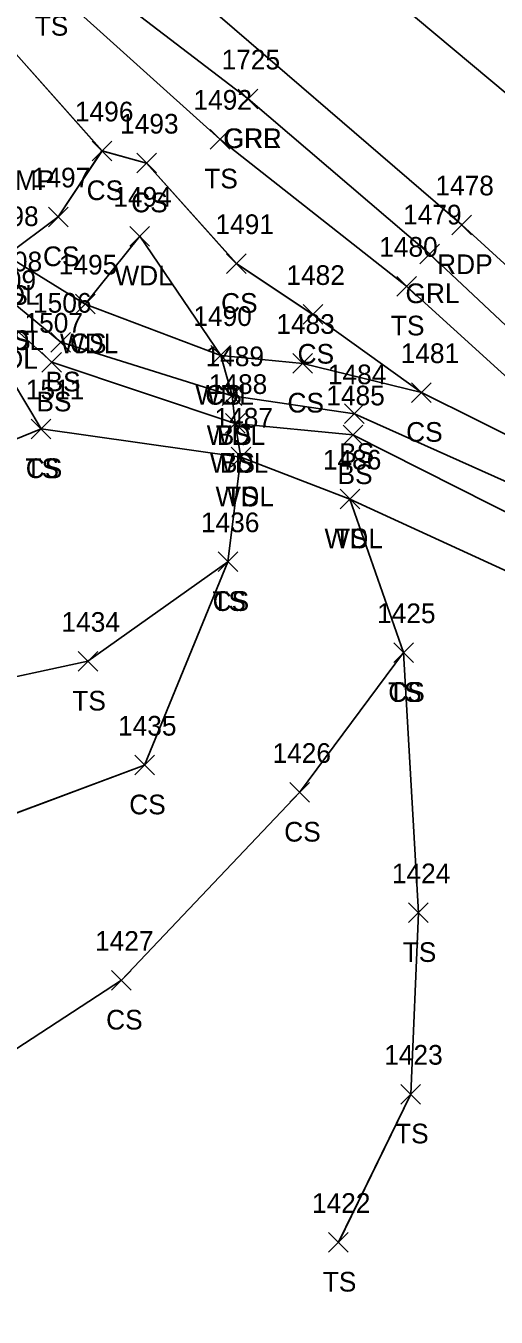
# Model space of a CAD drawing. Extents: x 1415642 to 1422021, y 544543 to 547232.
# Drawn here: x 1416137.5 to 1416185.4, y 546673.7 to 546804.9 of the extents above; entities that cross this region are included whole.
import ezdxf

# ---------------------------------------------------------------- set-up
doc = ezdxf.new("R2010")
doc.units = 0
for name, color, linetype in [('D_C', 7, 'Continuous'), ('L_A', 7, 'Continuous'), ('L_I', 7, 'Continuous'), ('L_TIC', 7, 'Continuous'), ('LAWA', 7, 'Continuous'), ('LELB', 7, 'Continuous'), ('P_A', 7, 'Continuous'), ('P_I', 7, 'Continuous'), ('P_TIC', 7, 'Continuous'), ('PET', 7, 'Continuous'), ('PRC', 7, 'Continuous'), ('R_A', 7, 'Continuous'), ('R_I', 7, 'Continuous'), ('R_TIC', 7, 'Continuous'), ('RGR', 7, 'Continuous')]:
    doc.layers.add(name, color=color, linetype=linetype)

msp = doc.modelspace()

# ---------------------------------------------------------------- linework, layer by layer
at = {"layer": 'L_TIC'}
for points in [[(1416156.26, 546792.38), (1416158.26, 546794.38)], [(1416158.26, 546792.38), (1416156.26, 546794.38)], [(1416144.27, 546791.19), (1416146.27, 546793.19)], [(1416146.27, 546791.19), (1416144.27, 546793.19)], [(1416144.27, 546791.19), (1416146.27, 546793.19)], [(1416146.27, 546791.19), (1416144.27, 546793.19)], [(1416148.8, 546789.95), (1416150.8, 546791.95)], [(1416150.8, 546789.95), (1416148.8, 546791.95)], [(1416139.83, 546784.48), (1416141.83, 546786.48)], [(1416141.83, 546784.48), (1416139.83, 546786.48)], [(1416148.11, 546782.52), (1416150.11, 546784.52)], [(1416150.11, 546782.52), (1416148.11, 546784.52)], [(1416157.94, 546779.74), (1416159.94, 546781.74)], [(1416159.94, 546779.74), (1416157.94, 546781.74)], [(1416175.24, 546777.44), (1416177.24, 546779.44)], [(1416177.24, 546777.44), (1416175.24, 546779.44)], [(1416142.57, 546775.63), (1416144.57, 546777.63)], [(1416144.57, 546775.63), (1416142.57, 546777.63)], [(1416142.57, 546775.63), (1416144.57, 546777.63)], [(1416144.57, 546775.63), (1416142.57, 546777.63)], [(1416165.72, 546774.57), (1416167.72, 546776.57)], [(1416167.72, 546774.57), (1416165.72, 546776.57)], [(1416140.08, 546771.75), (1416142.08, 546773.75)], [(1416142.08, 546771.75), (1416140.08, 546773.75)], [(1416156.34, 546770.4), (1416158.34, 546772.4)], [(1416158.34, 546770.4), (1416156.34, 546772.4)], [(1416156.34, 546770.4), (1416158.34, 546772.4)], [(1416158.34, 546770.4), (1416156.34, 546772.4)], [(1416139.16, 546769.72), (1416141.16, 546771.72)], [(1416141.16, 546769.72), (1416139.16, 546771.72)], [(1416164.69, 546769.6), (1416166.69, 546771.6)], [(1416166.69, 546769.6), (1416164.69, 546771.6)], [(1416176.76, 546766.63), (1416178.76, 546768.63)], [(1416178.76, 546766.63), (1416176.76, 546768.63)], [(1416176.76, 546766.63), (1416178.76, 546768.63)], [(1416178.76, 546766.63), (1416176.76, 546768.63)], [(1416157.5, 546766.31), (1416159.5, 546768.31)], [(1416159.5, 546766.31), (1416157.5, 546768.31)], [(1416157.5, 546766.31), (1416159.5, 546768.31)], [(1416159.5, 546766.31), (1416157.5, 546768.31)], [(1416169.94, 546764.48), (1416171.94, 546766.48)], [(1416171.94, 546764.48), (1416169.94, 546766.48)], [(1416138.08, 546762.94), (1416140.08, 546764.94)], [(1416140.08, 546762.94), (1416138.08, 546764.94)], [(1416138.08, 546762.94), (1416140.08, 546764.94)], [(1416140.08, 546762.94), (1416138.08, 546764.94)], [(1416157.82, 546763.49), (1416159.82, 546765.49)], [(1416159.82, 546763.49), (1416157.82, 546765.49)], [(1416157.82, 546763.49), (1416159.82, 546765.49)], [(1416159.82, 546763.49), (1416157.82, 546765.49)], [(1416169.78, 546762.33), (1416171.78, 546764.33)], [(1416171.78, 546762.33), (1416169.78, 546764.33)], [(1416158.4, 546760.07), (1416160.4, 546762.07)], [(1416160.4, 546760.07), (1416158.4, 546762.07)], [(1416158.4, 546760.07), (1416160.4, 546762.07)], [(1416160.4, 546760.07), (1416158.4, 546762.07)], [(1416169.48, 546755.81), (1416171.48, 546757.81)], [(1416171.48, 546755.81), (1416169.48, 546757.81)], [(1416169.48, 546755.81), (1416171.48, 546757.81)], [(1416171.48, 546755.81), (1416169.48, 546757.81)], [(1416157.08, 546749.44), (1416159.08, 546751.44)], [(1416159.08, 546749.44), (1416157.08, 546751.44)], [(1416157.08, 546749.44), (1416159.08, 546751.44)], [(1416159.08, 546749.44), (1416157.08, 546751.44)], [(1416174.94, 546740.2), (1416176.94, 546742.2)], [(1416176.94, 546740.2), (1416174.94, 546742.2)], [(1416174.94, 546740.2), (1416176.94, 546742.2)], [(1416176.94, 546740.2), (1416174.94, 546742.2)], [(1416142.84, 546739.32), (1416144.84, 546741.32)], [(1416144.84, 546739.32), (1416142.84, 546741.32)], [(1416148.6, 546728.77), (1416150.6, 546730.77)], [(1416150.6, 546728.77), (1416148.6, 546730.77)], [(1416164.36, 546726), (1416166.36, 546728)], [(1416166.36, 546726), (1416164.36, 546728)], [(1416176.44, 546713.77), (1416178.44, 546715.77)], [(1416178.44, 546713.77), (1416176.44, 546715.77)], [(1416146.25, 546706.9), (1416148.25, 546708.9)], [(1416148.25, 546706.9), (1416146.25, 546708.9)], [(1416175.66, 546695.33), (1416177.66, 546697.33)], [(1416177.66, 546695.33), (1416175.66, 546697.33)], [(1416168.31, 546680.27), (1416170.31, 546682.27)], [(1416170.31, 546680.27), (1416168.31, 546682.27)]]:
    msp.add_lwpolyline(points, dxfattribs=at)
at = {"layer": 'LAWA'}
for points in [[(1416189.47, 546748.09), (1416170.48, 546756.81), (1416159.4, 546761.07), (1416158.82, 546764.49), (1416158.5, 546767.31), (1416157.34, 546771.4), (1416149.11, 546783.52), (1416143.57, 546776.63), (1416135.57, 546781.55), (1416136.01, 546776.95), (1416135.4, 546775.05), (1416133.21, 546773.7), (1416124.82, 546771.25), (1416110.47, 546763.9), (1416099.19, 546751.92), (1416087.77, 546744.35), (1416077.13, 546736.35), (1416057.11, 546720.87), (1416047.17, 546704.92)], [(1416189.46, 546748.09), (1416170.49, 546756.81), (1416159.39, 546761.07), (1416158.81, 546764.5), (1416158.51, 546767.31), (1416157.34, 546771.4), (1416149.11, 546783.52), (1416143.57, 546776.63), (1416135.57, 546781.55), (1416136.01, 546776.96), (1416135.4, 546775.05), (1416133.22, 546773.7), (1416124.83, 546771.26), (1416110.48, 546763.9), (1416099.2, 546751.92), (1416087.78, 546744.35), (1416077.14, 546736.35), (1416057.11, 546720.87), (1416047.18, 546704.93)]]:
    msp.add_lwpolyline(points, dxfattribs=at)
at = {"layer": 'LELB'}
for points in [[(1416200.69, 546756.25), (1416177.76, 546767.63), (1416166.72, 546775.57), (1416158.94, 546780.74), (1416149.8, 546790.95), (1416145.27, 546792.19), (1416135.47, 546803.24), (1416119.09, 546819.38), (1416087.86, 546845.73), (1416058.66, 546867.92), (1416017.63, 546898.15), (1415975.94, 546926.54), (1415961.59, 546937.35), (1415930.25, 546967.22), (1415904.85, 546987.6), (1415883.27, 547005.7), (1415850.56, 547030.99), (1415821.69, 547055.02)], [(1416200.69, 546756.25), (1416177.77, 546767.63), (1416166.72, 546775.57), (1416158.93, 546780.74), (1416149.8, 546790.95), (1416145.28, 546792.19), (1416135.47, 546803.24), (1416119.09, 546819.38), (1416087.87, 546845.73), (1416058.67, 546867.92), (1416017.63, 546898.16), (1415975.95, 546926.55), (1415961.6, 546937.34), (1415930.25, 546967.22), (1415904.86, 546987.6), (1415883.28, 547005.7), (1415850.57, 547030.99), (1415821.7, 547055.02)], [(1416413.88, 546519.84), (1416385.73, 546558.12), (1416356.85, 546595.36), (1416336.82, 546621.39), (1416300.66, 546661.66), (1416278.22, 546684.25), (1416249.88, 546714.04), (1416230.93, 546728.9), (1416221.86, 546737.5), (1416200.69, 546756.25), (1416176.24, 546778.44), (1416157.26, 546793.38), (1416140.02, 546808.9), (1416121.84, 546825.58), (1416090.2, 546848.7), (1416061.67, 546872.28), (1416021.03, 546902.96), (1415979.27, 546932.57), (1415964.6, 546940.59)], [(1416413.88, 546519.84), (1416385.73, 546558.12), (1416356.85, 546595.36), (1416336.82, 546621.39), (1416300.66, 546661.66), (1416278.22, 546684.25), (1416249.88, 546714.04), (1416230.93, 546728.9), (1416221.87, 546737.51), (1416200.69, 546756.25), (1416176.24, 546778.44), (1416157.26, 546793.38), (1416140.03, 546808.9), (1416121.84, 546825.58), (1416090.21, 546848.7), (1416061.68, 546872.28), (1416021.04, 546902.96), (1415979.28, 546932.57), (1415964.61, 546940.59)], [(1416145.27, 546792.19), (1416140.83, 546785.48), (1416135.57, 546781.55), (1416134.13, 546786.33), (1416133.18, 546791.55), (1416133.27, 546797.31), (1416128.67, 546801.95), (1416121.92, 546800.59), (1416115.75, 546796.75), (1416101.26, 546800.37), (1416080.07, 546796.23), (1416060.24, 546785.43), (1416047.26, 546780.09), (1416047.59, 546762.69), (1416049.58, 546754.22), (1416036.94, 546750.51), (1416008.63, 546746.22)], [(1416145.28, 546792.19), (1416140.83, 546785.48), (1416135.57, 546781.55), (1416134.13, 546786.33), (1416133.18, 546791.55), (1416133.27, 546797.3), (1416128.68, 546801.95), (1416121.92, 546800.59), (1416115.75, 546796.75), (1416101.27, 546800.37), (1416080.08, 546796.22), (1416060.25, 546785.43), (1416047.26, 546780.09), (1416047.59, 546762.69), (1416049.58, 546754.22), (1416036.94, 546750.51), (1416008.64, 546746.22)], [(1416578, 546177.77), (1416578.55, 546199.27), (1416573.9, 546214.14), (1416552.43, 546269), (1416536.22, 546304.5), (1416520.22, 546335.71), (1416500.65, 546371.21), (1416484.25, 546405.14), (1416455.06, 546455.78), (1416435.93, 546486.65), (1416412.14, 546519.01), (1416383.64, 546557.13), (1416352.74, 546592.54), (1416331.82, 546618.14), (1416293.94, 546655.61), (1416274.22, 546680.91), (1416245.72, 546708.98), (1416224.27, 546729.93), (1416198.14, 546753.3), (1416170.94, 546765.48), (1416158.5, 546767.31), (1416141.08, 546772.75), (1416136.01, 546776.95), (1416129, 546780.64)], [(1416578, 546177.77), (1416578.55, 546199.27), (1416573.9, 546214.14), (1416552.42, 546269.01), (1416536.22, 546304.5), (1416520.22, 546335.71), (1416500.65, 546371.22), (1416484.25, 546405.15), (1416455.06, 546455.79), (1416435.93, 546486.65), (1416412.14, 546519.01), (1416383.65, 546557.13), (1416352.74, 546592.54), (1416331.82, 546618.14), (1416293.94, 546655.62), (1416274.22, 546680.91), (1416245.72, 546708.98), (1416224.27, 546729.93), (1416198.14, 546753.3), (1416170.94, 546765.48), (1416158.51, 546767.31), (1416141.09, 546772.75), (1416136.01, 546776.96), (1416129.01, 546780.64)], [(1416503.76, 546247.98), (1416498.74, 546274.69), (1416501.23, 546308.66), (1416502.98, 546324.04), (1416489.47, 546365.32), (1416480.57, 546403.46), (1416453.11, 546455.02), (1416433.2, 546484.78), (1416409.26, 546516.78), (1416378.25, 546552.92), (1416343.61, 546583.91), (1416327.57, 546614.09), (1416289.4, 546651.59), (1416267.58, 546675.69), (1416237.14, 546697.31), (1416220.66, 546725.9), (1416195.41, 546750.9), (1416170.78, 546763.33), (1416158.82, 546764.49), (1416140.16, 546770.72), (1416135.4, 546775.05), (1416128.27, 546778.63)], [(1416503.76, 546247.98), (1416498.74, 546274.69), (1416501.24, 546308.65), (1416502.98, 546324.03), (1416489.47, 546365.32), (1416480.57, 546403.46), (1416453.11, 546455.02), (1416433.2, 546484.78), (1416409.26, 546516.79), (1416378.25, 546552.92), (1416343.61, 546583.91), (1416327.58, 546614.09), (1416289.4, 546651.59), (1416267.58, 546675.69), (1416237.14, 546697.31), (1416220.66, 546725.9), (1416195.42, 546750.9), (1416170.78, 546763.33), (1416158.81, 546764.5), (1416140.16, 546770.72), (1416135.4, 546775.05), (1416128.28, 546778.62)], [(1416177.76, 546767.63), (1416165.69, 546770.6), (1416157.34, 546771.4), (1416143.57, 546776.63)], [(1416177.77, 546767.63), (1416165.69, 546770.6), (1416157.34, 546771.4), (1416143.57, 546776.63)], [(1416133.21, 546773.7), (1416139.08, 546763.94)], [(1416133.22, 546773.7), (1416139.08, 546763.94)], [(1416094.97, 546692.98), (1416100.91, 546725.02), (1416119.32, 546735.05), (1416143.84, 546740.32), (1416158.08, 546750.44), (1416159.4, 546761.07), (1416139.08, 546763.94), (1416114.01, 546753.75)], [(1416094.98, 546692.98), (1416100.92, 546725.02), (1416119.33, 546735.05), (1416143.84, 546740.32), (1416158.08, 546750.44), (1416159.39, 546761.07), (1416139.08, 546763.94), (1416114.01, 546753.75)], [(1416169.31, 546681.27), (1416176.66, 546696.33), (1416177.44, 546714.77), (1416175.94, 546741.2), (1416170.48, 546756.81)], [(1416169.32, 546681.28), (1416176.67, 546696.33), (1416177.44, 546714.77), (1416175.93, 546741.2), (1416170.49, 546756.81)], [(1416175.94, 546741.2), (1416165.36, 546727), (1416147.25, 546707.9), (1416122.51, 546691.8), (1416094.97, 546692.98), (1416111.6, 546712.58), (1416126.75, 546721.24), (1416149.6, 546729.77), (1416158.08, 546750.44)], [(1416175.93, 546741.2), (1416165.36, 546727), (1416147.26, 546707.91), (1416122.5, 546691.8), (1416094.98, 546692.98), (1416111.6, 546712.58), (1416126.75, 546721.25), (1416149.6, 546729.77), (1416158.08, 546750.44)]]:
    msp.add_lwpolyline(points, dxfattribs=at)
at = {"layer": 'P_TIC'}
for points in [[(1416180.86, 546783.67), (1416182.86, 546785.67)], [(1416182.86, 546783.67), (1416180.86, 546785.67)]]:
    msp.add_lwpolyline(points, dxfattribs=at)
at = {"layer": 'PET'}
for points in [[(1416417.68, 546520.98), (1416388.9, 546560.28), (1416359.4, 546597.75), (1416339.06, 546622.92), (1416303.08, 546664.45), (1416282.37, 546687.64), (1416253.58, 546717.16), (1416237.44, 546733.28), (1416206.51, 546762.17), (1416181.86, 546784.67), (1416151.94, 546810.47), (1416130.39, 546828.26), (1416101.49, 546851.34), (1416072.78, 546874.03), (1416047.41, 546892.82), (1416017.81, 546915.59), (1415982.21, 546942.39), (1415954.4, 546964.56)], [(1416417.68, 546520.98), (1416388.9, 546560.28), (1416359.4, 546597.76), (1416339.06, 546622.93), (1416303.08, 546664.45), (1416282.37, 546687.65), (1416253.58, 546717.16), (1416237.44, 546733.28), (1416206.51, 546762.17), (1416181.87, 546784.67), (1416151.94, 546810.47), (1416130.39, 546828.26), (1416101.49, 546851.34), (1416072.78, 546874.03), (1416047.41, 546892.82), (1416017.81, 546915.59), (1415982.21, 546942.39), (1415954.4, 546964.56)]]:
    msp.add_lwpolyline(points, dxfattribs=at)
at = {"layer": 'PRC'}
for points in [[(1416425.29, 546532.23), (1416399.16, 546568.17), (1416370.34, 546605), (1416349.98, 546630.03), (1416312.55, 546673.44), (1416291.21, 546696.63), (1416262.58, 546725.99), (1416246.66, 546742.06), (1416214.68, 546772.43), (1416190.4, 546794.67), (1416160.38, 546819.82), (1416139.01, 546837.64), (1416109.6, 546860.71), (1416080.51, 546883.13), (1416051.44, 546902.01), (1416024.84, 546926.07), (1415989.92, 546951.67), (1415962.46, 546973.18)], [(1416425.29, 546532.24), (1416399.16, 546568.17), (1416370.35, 546605), (1416349.98, 546630.03), (1416312.55, 546673.45), (1416291.21, 546696.63), (1416262.58, 546725.99), (1416246.66, 546742.06), (1416214.67, 546772.43), (1416190.4, 546794.67), (1416160.38, 546819.82), (1416139.01, 546837.64), (1416109.6, 546860.71), (1416080.51, 546883.13), (1416051.45, 546902.01), (1416024.84, 546926.07), (1415989.92, 546951.68), (1415962.46, 546973.18)]]:
    msp.add_lwpolyline(points, dxfattribs=at)
at = {"layer": 'R_TIC'}
for points in [[(1416159.13, 546796.47), (1416161.13, 546798.47)], [(1416161.13, 546796.47), (1416159.13, 546798.47)], [(1416159.13, 546796.47), (1416161.13, 546798.47)], [(1416161.13, 546796.47), (1416159.13, 546798.47)], [(1416177.59, 546780.72), (1416179.59, 546782.72)], [(1416179.59, 546780.72), (1416177.59, 546782.72)]]:
    msp.add_lwpolyline(points, dxfattribs=at)
at = {"layer": 'RGR'}
for points in [[(1415969.74, 546941.99), (1415991.65, 546929.21), (1416016.29, 546910.93), (1416041.47, 546892.17), (1416068.82, 546871.25), (1416092.52, 546852.68), (1416119.85, 546831.08), (1416143.05, 546810.55), (1416160.13, 546797.47)], [(1415969.75, 546941.99), (1415991.65, 546929.21), (1416016.3, 546910.93), (1416041.48, 546892.18), (1416068.83, 546871.25), (1416092.52, 546852.68), (1416119.86, 546831.08), (1416143.05, 546810.55), (1416160.13, 546797.47)], [(1416221.86, 546737.5), (1416203.53, 546758.32), (1416178.59, 546781.72), (1416160.13, 546797.47)], [(1416221.87, 546737.51), (1416203.53, 546758.32), (1416178.59, 546781.72), (1416160.13, 546797.47)]]:
    msp.add_lwpolyline(points, dxfattribs=at)

# ---------------------------------------------------------------- texts
at = {"layer": 'D_C'}
msp.add_text("11'X16' CGMP", height=2, dxfattribs=at).set_placement((1416122.92, 546788.22))
at = {"layer": 'L_A'}
for s, p in [('TS', (1416138.43, 546803.9)), ('TS', (1416155.67, 546788.38)), ('CS', (1416143.71, 546787.19)), ('CS', (1416143.71, 546787.19)), ('CS', (1416148.24, 546785.95)), ('CS', (1416139.27, 546780.48)), ('WDL', (1416146.53, 546778.52)), ('WDL', (1416132.99, 546776.55)), ('CS', (1416134.01, 546776.55)), ('CS', (1416157.38, 546775.74)), ('TS', (1416174.65, 546773.44)), ('WDL', (1416133.43, 546771.95)), ('BS', (1416134.45, 546771.95)), ('CS', (1416142.01, 546771.63)), ('WDL', (1416140.99, 546771.63)), ('CS', (1416165.16, 546770.57)), ('WDL', (1416132.81, 546770.05)), ('BS', (1416139.53, 546767.75)), ('WDL', (1416154.76, 546766.4)), ('CS', (1416155.78, 546766.4)), ('BS', (1416138.6, 546765.72)), ('CS', (1416164.13, 546765.6)), ('CS', (1416176.2, 546762.63)), ('CS', (1416176.2, 546762.63)), ('WDL', (1416155.92, 546762.31)), ('BS', (1416156.94, 546762.31)), ('BS', (1416169.38, 546760.48)), ('TS', (1416137.49, 546758.94)), ('CS', (1416137.52, 546758.94)), ('WDL', (1416156.24, 546759.49)), ('BS', (1416157.26, 546759.49)), ('BS', (1416169.22, 546758.33)), ('WDL', (1416156.82, 546756.07)), ('TS', (1416157.81, 546756.07)), ('WDL', (1416167.9, 546751.81)), ('TS', (1416168.89, 546751.81)), ('TS', (1416156.49, 546745.44)), ('CS', (1416156.52, 546745.44)), ('TS', (1416174.35, 546736.2)), ('CS', (1416174.38, 546736.2)), ('TS', (1416142.25, 546735.32)), ('CS', (1416148.04, 546724.77)), ('CS', (1416163.8, 546722)), ('TS', (1416175.85, 546709.77)), ('CS', (1416145.69, 546702.9)), ('TS', (1416175.07, 546691.33)), ('TS', (1416167.72, 546676.27))]:
    msp.add_text(s, height=2, dxfattribs=at).set_placement(p)
at = {"layer": 'L_I'}
for s, p in [('1492', (1416154.57, 546796.38)), ('1496', (1416142.52, 546795.19)), ('1496', (1416142.52, 546795.19)), ('1493', (1416147.11, 546793.95)), ('1497', (1416138.13, 546788.48)), ('1494', (1416146.42, 546786.52)), ('1498', (1416132.88, 546784.55)), ('1498', (1416132.88, 546784.55)), ('1491', (1416156.81, 546783.74)), ('1480', (1416173.46, 546781.44)), ('1508', (1416133.24, 546779.95)), ('1508', (1416133.24, 546779.95)), ('1495', (1416140.88, 546779.63)), ('1495', (1416140.88, 546779.63)), ('1482', (1416164.02, 546778.57)), ('1509', (1416132.62, 546778.05)), ('1509', (1416132.62, 546778.05)), ('1506', (1416138.26, 546775.75)), ('1490', (1416154.56, 546774.4)), ('1490', (1416154.56, 546774.4)), ('1507', (1416137.39, 546773.72)), ('1483', (1416163, 546773.6)), ('1489', (1416155.8, 546770.31)), ('1489', (1416155.8, 546770.31)), ('1481', (1416175.64, 546770.63)), ('1481', (1416175.64, 546770.63)), ('1484', (1416168.24, 546768.48)), ('1511', (1416137.52, 546766.94)), ('1511', (1416137.52, 546766.94)), ('1488', (1416156.13, 546767.49)), ('1488', (1416156.13, 546767.49)), ('1485', (1416168.08, 546766.33)), ('1487', (1416156.71, 546764.07)), ('1487', (1416156.71, 546764.07)), ('1486', (1416167.73, 546759.81)), ('1486', (1416167.73, 546759.81)), ('1436', (1416155.33, 546753.44)), ('1436', (1416155.33, 546753.44)), ('1425', (1416173.24, 546744.2)), ('1425', (1416173.24, 546744.2)), ('1434', (1416141.15, 546743.32)), ('1435', (1416146.9, 546732.77)), ('1426', (1416162.61, 546730)), ('1424', (1416174.75, 546717.77)), ('1427', (1416144.56, 546710.9)), ('1423', (1416173.97, 546699.33)), ('1422', (1416166.62, 546684.27))]:
    msp.add_text(s, height=2, dxfattribs=at).set_placement(p)
at = {"layer": 'P_A'}
msp.add_text('RDP', height=2, dxfattribs=at).set_placement((1416179.35, 546779.67))
at = {"layer": 'P_I'}
msp.add_text('1478', height=2, dxfattribs=at).set_placement((1416179.17, 546787.67))
at = {"layer": 'R_A'}
for s, p in [('GRR', (1416157.61, 546792.47)), ('GRL', (1416157.67, 546792.47)), ('GRL', (1416176.13, 546776.72))]:
    msp.add_text(s, height=2, dxfattribs=at).set_placement(p)
at = {"layer": 'R_I'}
for s, p in [('1725', (1416157.43, 546800.47)), ('1725', (1416157.43, 546800.47)), ('1479', (1416175.89, 546784.72))]:
    msp.add_text(s, height=2, dxfattribs=at).set_placement(p)

doc.saveas('drawing.dxf')
